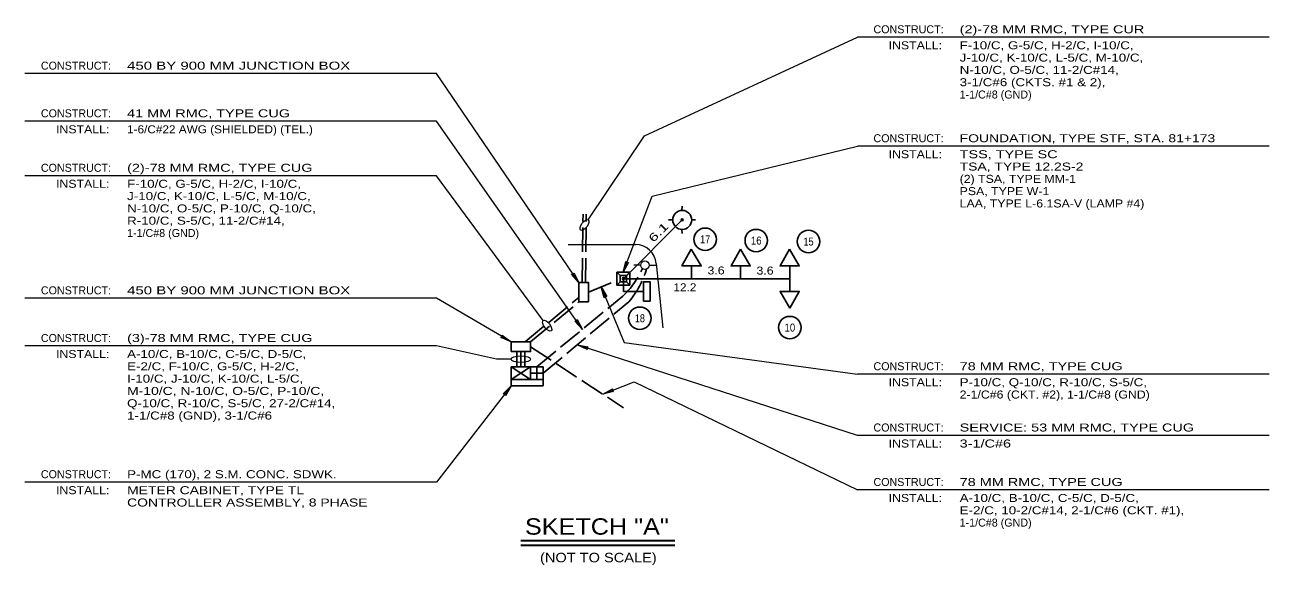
# Model space of a CAD drawing. Extents: x 168203 to 169864, y 223196 to 223870.
# Drawn here: x 168644.5 to 168735.8, y 223388.5 to 223428.2 of the extents above; entities that cross this region are included whole.
import ezdxf
from ezdxf.enums import TextEntityAlignment as Align

# ---------------------------------------------------------------- set-up
doc = ezdxf.new("R2010")
doc.units = 0
doc.header["$LTSCALE"] = 0.3
doc.header["$PDMODE"] = 32
doc.header["$PDSIZE"] = 0.15
doc.linetypes.add('LONG_DASHED', pattern=[7.5, 6, -1.5])
for name, color, linetype, lineweight in [('1', 7, 'Continuous', 13), ('10', 7, 'Continuous', 13), ('32', 7, 'Continuous', 25), ('4', 7, 'Continuous', 25), ('6', 7, 'Continuous', 25), ('8', 7, 'Continuous', 25), ('9', 7, 'Continuous', 13)]:
    doc.layers.add(name, color=color, linetype=linetype, lineweight=lineweight)

msp = doc.modelspace()

# ---------------------------------------------------------------- linework, layer by layer
at = {"layer": '1'}
for p, q in [((168684.4082, 223412.0372), (168689.3593, 223412.0372)), ((168690.8555, 223410.6453), (168691.3411, 223405.9231)), ((168689.7236, 223410.5295), (168689.2236, 223410.5295)), ((168690.3486, 223410.5295), (168690.8486, 223410.5295))]:
    msp.add_line(p, q, dxfattribs=at)
msp.add_circle((168690.0361, 223410.5295), 0.3125, dxfattribs=at)
msp.add_arc((168689.3593, 223410.5372), 1.5, 4.13349, 90.00005, dxfattribs=at)
at = {"layer": '10'}
for p, q in [((168735.8375, 223427.2662), (168705.6297, 223427.2662)), ((168674.7418, 223424.5965), (168644.534, 223424.5965)), ((168685.1864, 223409.2466), (168674.7418, 223424.5965)), ((168674.7418, 223421.0965), (168644.534, 223421.0965)), ((168685.4457, 223405.8152), (168674.7418, 223421.0965)), ((168735.8375, 223419.2662), (168705.6297, 223419.2662)), ((168674.7418, 223417.0965), (168644.534, 223417.0965)), ((168682.5718, 223406.4583), (168674.7418, 223417.0965)), ((168674.7418, 223408.0965), (168644.534, 223408.0965)), ((168680.2189, 223404.8941), (168674.7418, 223408.0965)), ((168674.7418, 223404.5965), (168644.534, 223404.5965)), ((168735.8375, 223402.5247), (168705.6297, 223402.5247)), ((168680.2184, 223401.6586), (168674.7418, 223394.5965)), ((168674.7418, 223394.5965), (168644.534, 223394.5965)), ((168735.8375, 223394.0247), (168705.6297, 223394.0247))]:
    msp.add_line(p, q, dxfattribs=at)
for points in [[(168685.8686, 223413.8609), (168689.9984, 223420.0364), (168705.6297, 223427.2662)], [(168688.4473, 223410.0071), (168690.5609, 223415.5865), (168705.6297, 223419.2662)], [(168686.8268, 223408.9276), (168688.5107, 223404.8546), (168705.6297, 223402.5247)], [(168680.2142, 223403.6181), (168679.151, 223403.618), (168674.7418, 223404.5965)], [(168735.8375, 223398.0247), (168705.6297, 223398.0247), (168685.0632, 223404.6804)], [(168686.9396, 223401.05), (168689.248, 223401.9513), (168705.6297, 223394.0247)]]:
    msp.add_lwpolyline(points, dxfattribs=at)
for points in [[(168688.8284, 223410.7324), (168688.4473, 223410.0071), (168688.634, 223410.8061), (168688.7066, 223410.6915)], [(168684.8111, 223409.9749), (168685.1864, 223409.2466), (168684.6393, 223409.858), (168684.7747, 223409.8517)], [(168687.0457, 223408.138), (168686.8268, 223408.9276), (168687.2377, 223408.2174), (168687.1064, 223408.2512)], [(168685.0605, 223406.5384), (168685.4457, 223405.8152), (168684.8903, 223406.4191), (168685.0258, 223406.4147)], [(168679.567, 223405.3904), (168680.2189, 223404.8941), (168679.4621, 223405.211), (168679.5871, 223405.2635)], [(168685.8064, 223404.3354), (168685.0632, 223404.6804), (168685.8704, 223404.5331), (168685.7595, 223404.4551)], [(168679.6414, 223401.0768), (168680.2184, 223401.6586), (168679.8057, 223400.9495), (168679.7699, 223401.0802)], [(168687.7334, 223401.2532), (168686.9396, 223401.05), (168687.6578, 223401.4468), (168687.6214, 223401.3162)]]:
    msp.add_lwpolyline(points, close=True, dxfattribs=at)
for centre, major_axis, ratio in [((168685.593, 223413.4775), (-0.2756, -0.3835), 0.453047), ((168682.864, 223406.0826), (-0.2922, 0.3757), 0.448277), ((168680.9282, 223403.6243), (0.714, 0.0062), 0.338213)]:
    msp.add_ellipse(centre, major_axis=major_axis, ratio=ratio, dxfattribs=at)
at = {"layer": '32'}
for p, q in [((168688.4563, 223409.5372), (168692.7697, 223413.8506)), ((168693.4563, 223409.5372), (168693.4563, 223410.477)), ((168697.0563, 223409.5372), (168697.0563, 223410.477)), ((168688.4563, 223408.5974), (168688.4563, 223409.5372)), ((168700.6563, 223409.5372), (168700.6563, 223408.5974)), ((168688.4563, 223408.5974), (168689.9392, 223408.5974))]:
    msp.add_line(p, q, dxfattribs=at)
for points in [[(168693.4382, 223411.6968), (168692.7515, 223410.477), (168693.4563, 223410.477), (168694.1611, 223410.477)], [(168697.0382, 223411.6968), (168696.3515, 223410.477), (168697.0563, 223410.477), (168697.7611, 223410.477)], [(168700.6382, 223411.6968), (168699.9515, 223410.477), (168700.6563, 223410.477), (168701.3611, 223410.477)], [(168690.409, 223407.8881), (168690.409, 223409.3068), (168689.9392, 223409.3068), (168689.9392, 223407.8881)], [(168700.6744, 223407.3776), (168701.3611, 223408.5974), (168700.6563, 223408.5974), (168699.9515, 223408.5974)]]:
    msp.add_lwpolyline(points, close=True, dxfattribs=at)
msp.add_lwpolyline([(168688.4563, 223409.5372), (168700.6563, 223409.5372), (168700.6563, 223410.477)], dxfattribs=at)
for centre in [(168694.4555, 223412.4268), (168698.2014, 223412.3337), (168702.0404, 223412.2639), (168689.6626, 223406.6306), (168700.669, 223405.9457)]:
    msp.add_circle(centre, 0.8236, dxfattribs=at)
at = {"layer": '4'}
for p, q in [((168687.9774, 223410.0071), (168688.2124, 223409.7721)), ((168688.9172, 223410.0071), (168688.6822, 223409.7721)), ((168687.9774, 223409.0673), (168688.2124, 223409.3023)), ((168688.9172, 223409.0673), (168688.6822, 223409.3023))]:
    msp.add_line(p, q, dxfattribs=at)
for points in [[(168687.9774, 223410.0071), (168687.9774, 223409.0673), (168688.9172, 223409.0673), (168688.9172, 223410.0071)], [(168688.2124, 223409.7721), (168688.6822, 223409.7721), (168688.6822, 223409.3023), (168688.2124, 223409.3023)]]:
    msp.add_lwpolyline(points, close=True, dxfattribs=at)
msp.add_point((168688.4563, 223409.5372), dxfattribs=at)
at = {"layer": '6', "linetype": 'LONG_DASHED'}
for p, q in [((168685.4307, 223409.2466), (168685.4911, 223414.2809)), ((168685.669, 223409.2466), (168685.7294, 223414.2781)), ((168685.9002, 223408.5373), (168687.9774, 223409.4122)), ((168681.2373, 223404.8941), (168685.1864, 223408.1588)), ((168681.6376, 223404.8941), (168685.1864, 223407.8279)), ((168682.1069, 223403.0683), (168688.4013, 223408.2467)), ((168682.5678, 223402.5984), (168688.8574, 223407.8459)), ((168680.6326, 223404.1803), (168680.6326, 223403.0683)), ((168680.9282, 223404.1803), (168680.9282, 223403.0683)), ((168681.232, 223404.1803), (168681.232, 223403.0683)), ((168681.6376, 223404.5372), (168688.4522, 223400.0552))]:
    msp.add_line(p, q, dxfattribs=at)
at = {"layer": '6'}
for p, q in [((168680.2184, 223403.0683), (168681.628, 223402.1285)), ((168681.628, 223403.0683), (168680.2184, 223402.1285)), ((168680.2184, 223403.0683), (168682.5678, 223403.0683)), ((168680.2184, 223403.0683), (168680.2184, 223402.1285)), ((168681.628, 223402.1285), (168681.628, 223403.0683)), ((168681.628, 223402.5984), (168682.5678, 223402.5984)), ((168682.1069, 223403.0683), (168682.1069, 223402.1285)), ((168682.5678, 223403.0683), (168682.5678, 223402.1285)), ((168682.5678, 223402.1285), (168680.2184, 223402.1285)), ((168680.2184, 223402.1285), (168680.2184, 223401.6586)), ((168682.5678, 223401.6586), (168680.2184, 223401.6586)), ((168682.5678, 223402.1285), (168682.5678, 223401.6586))]:
    msp.add_line(p, q, dxfattribs=at)
for points in [[(168685.9002, 223407.8279), (168685.1864, 223407.8279), (168685.1864, 223409.2466), (168685.9002, 223409.2466)], [(168680.2189, 223404.1803), (168680.2189, 223404.8941), (168681.6376, 223404.8941), (168681.6376, 223404.1803)]]:
    msp.add_lwpolyline(points, close=True, dxfattribs=at)
at = {"layer": '6', "linetype": 'LONG_DASHED'}
for centre, radius, start, end in [((168684.0978, 223412.8293), 6.2865, 313.20139, 336.09784), ((168683.7004, 223412.1673), 6.7282, 320.03766, 343.32646)]:
    msp.add_arc(centre, radius, start, end, dxfattribs=at)
at = {"layer": '8'}
for p, q in [((168692.7537, 223414.5438), (168692.7601, 223414.857)), ((168691.7569, 223413.8538), (168692.0764, 223413.8538)), ((168693.4694, 223413.8538), (168693.7568, 223413.8602)), ((168692.7601, 223412.8635), (168692.7537, 223413.151))]:
    msp.add_line(p, q, dxfattribs=at)
msp.add_circle((168692.7697, 223413.8506), 0.6965, dxfattribs=at)
msp.add_point((168692.7665, 223413.8538), dxfattribs=at)
at = {"layer": '9', "lineweight": 35}
for p, q in [((168680.917, 223390.3044), (168692.2328, 223390.3044)), ((168680.917, 223389.957), (168692.2328, 223389.957))]:
    msp.add_line(p, q, dxfattribs=at)

# ---------------------------------------------------------------- texts
at = {"layer": '10'}
for s, p in [('CONSTRUCT:', (168706.8044, 223427.5554)), ('CONSTRUCT:', (168645.7087, 223424.8857)), ('1-1/C#8 (GND)           ', (168713.1297, 223422.7662)), ('CONSTRUCT:', (168645.7087, 223421.3857)), ('CONSTRUCT:', (168706.8044, 223419.5554)), ('CONSTRUCT:', (168645.7087, 223417.3857)), ('1-1/C#8 (GND)                  ', (168652.034, 223412.5965)), ('CONSTRUCT:', (168645.7087, 223408.3857)), ('CONSTRUCT:', (168645.7087, 223404.8857)), ('CONSTRUCT:', (168706.8044, 223402.8139)), ('CONSTRUCT:', (168706.8044, 223398.3139)), ('CONSTRUCT:', (168645.7087, 223394.8857)), ('CONSTRUCT:', (168706.8044, 223394.3139)), ('1-1/C#8 (GND)                       ', (168713.1297, 223391.3318))]:
    msp.add_text(s, height=0.5873, dxfattribs=at).set_placement(p)
for s, width, p in [('(2)-78 MM RMC, TYPE CUR              ', 1.35, (168713.1297, 223427.5554)), ('F-10/C, G-5/C, H-2/C, I-10/C,', 1.25, (168713.1297, 223426.3807)), ('J-10/C, K-10/C, L-5/C, M-10/C,', 1.25, (168713.1297, 223425.477)), ('450 BY 900 MM JUNCTION BOX           ', 1.4, (168652.034, 223424.8857)), ('N-10/C, O-5/C, 11-2/C#14,  ', 1.25, (168713.1297, 223424.5734)), ('3-1/C#6 (CKTS. #1 & 2),  ', 1.25, (168713.1297, 223423.6698)), ('41 MM RMC, TYPE CUG                  ', 1.35, (168652.034, 223421.3857)), ('1-6/C#22 AWG (SHIELDED) (TEL.)        ', 1.1, (168652.034, 223420.211)), ('FOUNDATION, TYPE STF, STA. 81+173     ', 1.3, (168713.1297, 223419.5554)), ('TSS, TYPE SC                         ', 1.35, (168713.1297, 223418.3807)), ('(2)-78 MM RMC, TYPE CUG              ', 1.35, (168652.034, 223417.3857)), ('TSA, TYPE 12.2S-2                    ', 1.3, (168713.1297, 223417.477)), ('(2) TSA, TYPE MM-1                   ', 1.15, (168713.1297, 223416.5734)), ('F-10/C, G-5/C, H-2/C, I-10/C,', 1.25, (168652.034, 223416.211)), ('PSA, TYPE W-1                    ', 1.15, (168713.1297, 223415.6698)), ('J-10/C, K-10/C, L-5/C, M-10/C,', 1.25, (168652.034, 223415.3073)), ('LAA, TYPE L-6.1SA-V (LAMP #4)         ', 1.15, (168713.1297, 223414.7662)), ('N-10/C, O-5/C, P-10/C, Q-10/C,  ', 1.25, (168652.034, 223414.4037)), ('R-10/C, S-5/C, 11-2/C#14,       ', 1.25, (168652.034, 223413.5001)), ('450 BY 900 MM JUNCTION BOX           ', 1.4, (168652.034, 223408.3857)), ('(3)-78 MM RMC, TYPE CUG                ', 1.35, (168652.034, 223404.8857)), ('A-10/C, B-10/C, C-5/C, D-5/C,', 1.25, (168652.034, 223403.711)), ('E-2/C, F-10/C, G-5/C, H-2/C,  ', 1.25, (168652.034, 223402.8073)), ('78 MM RMC, TYPE CUG                  ', 1.35, (168713.1297, 223402.8139)), ('I-10/C, J-10/C, K-10/C, L-5/C,', 1.25, (168652.034, 223401.9037)), ('M-10/C, N-10/C, O-5/C, P-10/C, ', 1.3, (168652.034, 223401.0001)), ('P-10/C, Q-10/C, R-10/C, S-5/C,', 1.25, (168713.1297, 223401.6392)), ('Q-10/C, R-10/C, S-5/C, 27-2/C#14, ', 1.25, (168652.034, 223400.0965)), ('2-1/C#6 (CKT. #2), 1-1/C#8 (GND)   ', 1.15, (168713.1297, 223400.7355)), ('1-1/C#8 (GND), 3-1/C#6           ', 1.25, (168652.034, 223399.1929)), ('SERVICE: 53 MM RMC, TYPE CUG         ', 1.35, (168713.1297, 223398.3139)), ('3-1/C#6                               ', 1.35, (168713.1297, 223397.1392)), ('P-MC (170), 2 S.M. CONC. SDWK.         ', 1.25, (168652.034, 223394.8857)), ('METER CABINET, TYPE TL               ', 1.3, (168652.034, 223393.711)), ('78 MM RMC, TYPE CUG                  ', 1.35, (168713.1297, 223394.3139)), ('CONTROLLER ASSEMBLY, 8 PHASE         ', 1.3, (168652.034, 223392.8073)), ('A-10/C, B-10/C, C-5/C, D-5/C,', 1.25, (168713.1297, 223393.1392)), ('E-2/C, 10-2/C#14, 2-1/C#6 (CKT. #1), ', 1.25, (168713.1297, 223392.2355))]:
    msp.add_text(s, height=0.5873, dxfattribs=dict(at, width=width)).set_placement(p)
at = {"layer": '10', "width": 1.15}
for p in [(168711.8316, 223426.3807), (168650.7359, 223420.211), (168711.8316, 223418.3807), (168650.7359, 223416.211), (168650.7359, 223403.711), (168711.8316, 223401.6392), (168711.8316, 223397.1392), (168650.7359, 223393.711), (168711.8316, 223393.1392)]:
    msp.add_text('INSTALL:', height=0.5873, dxfattribs=at).set_placement(p, align=Align.RIGHT)
at = {"layer": '32', "width": 1.5}
msp.add_text('6.1', height=0.5873, rotation=45, dxfattribs=at).set_placement((168691.231, 223412.7362), align=Align.CENTER)
at = {"layer": '32'}
for s, width, p in [('17', 0.85, (168694.4555, 223412.1332)), ('16', 0.9, (168698.2014, 223412.0401)), ('15', 0.85, (168702.0404, 223411.9703)), ('3.6', 1.15, (168695.2532, 223409.8468)), ('3.6', 1.15, (168698.8479, 223409.8372)), ('12.2', 1.1, (168692.969, 223408.6108)), ('18', 0.85, (168689.6626, 223406.337)), ('10', 0.9, (168700.669, 223405.6521))]:
    msp.add_text(s, height=0.5873, dxfattribs=dict(at, width=width)).set_placement(p, align=Align.CENTER)
at = {"layer": '9', "width": 1.15}
msp.add_text('SKETCH "A"', height=1.202, dxfattribs=at).set_placement((168686.5083, 223390.7381), align=Align.CENTER)
msp.add_text('(NOT TO SCALE)', height=0.6958, dxfattribs=at).set_placement((168682.3351, 223388.7115))

doc.saveas('drawing.dxf')
